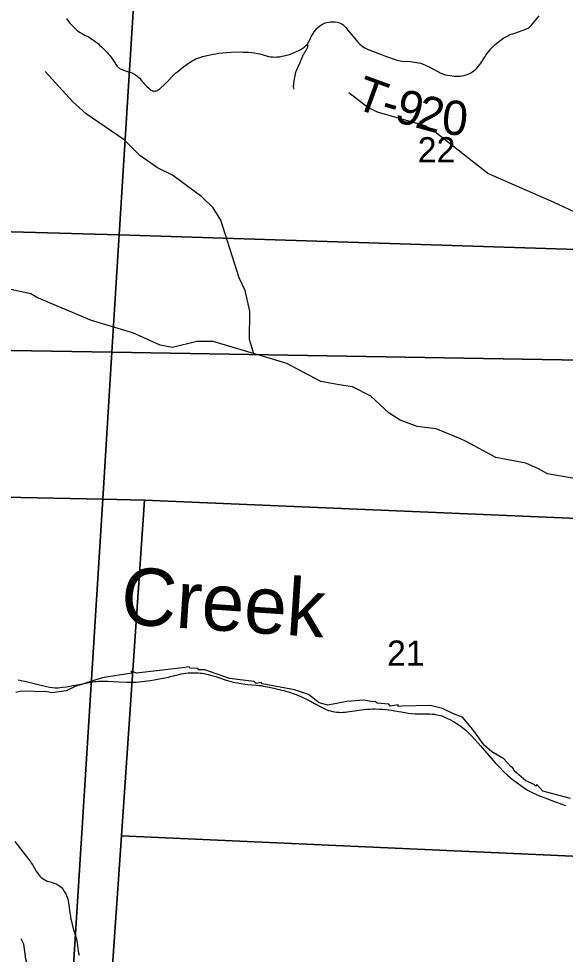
# Model space of a CAD drawing. Extents: x -2.1 to 31.9, y 6.3 to 28.3.
# Drawn here: x 1.171 to 2.076, y 21.978 to 23.525 of the extents above; entities that cross this region are included whole.
import ezdxf

# ---------------------------------------------------------------- set-up
doc = ezdxf.new("R2010")
doc.units = 0
for name, color, linetype in [('GM_X_County_Road', 7, 'Continuous'), ('GM_X_Minor_River', 7, 'Continuous'), ('GM_X_Minor_River_Text', 7, 'Continuous'), ('GM_X_Section', 7, 'Continuous'), ('GM_X_Section_Text', 7, 'Continuous'), ('GM_X_Township_Road', 7, 'Continuous'), ('GM_X_Township_Road_Text', 7, 'Continuous')]:
    doc.layers.add(name, color=color, linetype=linetype)

msp = doc.modelspace()

# ---------------------------------------------------------------- linework, layer by layer
at = {"layer": 'GM_X_County_Road'}
for points in [[(1.3504, 22.4281), (1.3554, 22.4281), (1.3656, 22.4282), (1.3701, 22.4286), (1.3749, 22.4291), (1.3895, 22.4309), (1.3952, 22.4318), (1.4009, 22.4327), (1.4165, 22.4357), (1.4193, 22.4363), (1.4224, 22.4372), (1.4369, 22.4409), (1.4403, 22.4416), (1.444, 22.4423), (1.4479, 22.4428), (1.4519, 22.4432), (1.4562, 22.4434), (1.4607, 22.4434), (1.4651, 22.4433), (1.4689, 22.4432), (1.4719, 22.4429), (1.4749, 22.4426), (1.4774, 22.4422), (1.4803, 22.4416), (1.4846, 22.4407), (1.4887, 22.4397), (1.4925, 22.4387), (1.4976, 22.4371), (1.511, 22.4325), (1.5169, 22.4307), (1.5207, 22.4296), (1.5247, 22.4285), (1.5291, 22.4275), (1.5333, 22.4266), (1.5392, 22.4256), (1.5426, 22.4251), (1.5462, 22.4246), (1.5502, 22.4242), (1.5643, 22.4231), (1.5686, 22.4227), (1.5725, 22.4222), (1.5759, 22.4216), (1.5862, 22.4198), (1.5981, 22.4172), (1.6102, 22.4142), (1.6207, 22.4109), (1.6303, 22.4074), (1.638, 22.4042), (1.6473, 22.4001), (1.6539, 22.3966), (1.6606, 22.3929), (1.6734, 22.3859), (1.6787, 22.3834), (1.684, 22.3813), (1.6874, 22.3803), (1.6909, 22.3794), (1.6941, 22.3787), (1.6976, 22.3782), (1.701, 22.3781), (1.7044, 22.378), (1.7082, 22.3781), (1.7117, 22.3784), (1.7147, 22.3788), (1.7347, 22.3818), (1.7386, 22.3824), (1.7427, 22.3828), (1.7474, 22.3832), (1.7526, 22.3835), (1.7568, 22.3836), (1.7612, 22.3836), (1.7675, 22.3835), (1.7736, 22.3833), (1.7785, 22.3829), (1.7832, 22.3824), (1.7883, 22.3816), (1.7937, 22.3807), (1.8109, 22.3777), (1.816, 22.3769), (1.8214, 22.3762), (1.827, 22.3758), (1.8327, 22.3756), (1.8515, 22.3754), (1.8554, 22.3752), (1.8593, 22.3749), (1.8633, 22.3741), (1.8671, 22.3732), (1.8715, 22.372), (1.8759, 22.3703), (1.881, 22.3681), (1.8857, 22.3656), (1.891, 22.3627), (1.8977, 22.3585), (1.9037, 22.3544), (1.9091, 22.3501), (1.9145, 22.3452), (1.9216, 22.338), (1.9354, 22.3228), (1.9597, 22.2948), (1.9673, 22.2866), (1.9735, 22.2804), (1.9803, 22.274), (1.988, 22.2676), (1.9983, 22.2596), (2.0059, 22.2542), (2.0133, 22.2494), (2.0198, 22.2458), (2.0231, 22.2442), (2.0268, 22.2426), (2.0305, 22.241), (2.0345, 22.2394), (2.0535, 22.2325), (2.0642, 22.2285), (2.0759, 22.2238)], [(1.1705, 22.4319), (1.1755, 22.4308), (1.1811, 22.4295), (1.199, 22.4251), (1.217, 22.4206), (1.2222, 22.4196), (1.2269, 22.419), (1.2318, 22.4187), (1.2364, 22.4188), (1.2438, 22.4195), (1.2496, 22.4204), (1.271, 22.4243), (1.2907, 22.428), (1.2938, 22.4286), (1.2967, 22.429), (1.3, 22.4293), (1.3032, 22.4295), (1.3075, 22.4297), (1.3119, 22.4297), (1.3155, 22.4297), (1.3188, 22.4295), (1.3363, 22.4284), (1.3504, 22.4281)], [(1.165, 22.1642), (1.1779, 22.1472), (1.1894, 22.1322), (1.1911, 22.1301), (1.1925, 22.1282), (1.1944, 22.1253), (1.2001, 22.1155), (1.2016, 22.1134), (1.203, 22.1115), (1.2064, 22.1073), (1.2086, 22.1051), (1.211, 22.1031), (1.2131, 22.1016), (1.2158, 22.1002), (1.2185, 22.099), (1.2213, 22.0981), (1.2248, 22.097), (1.2276, 22.0962), (1.2305, 22.0953), (1.2334, 22.0942), (1.2362, 22.0928), (1.2393, 22.0908), (1.242, 22.0884), (1.2447, 22.0851), (1.2467, 22.082), (1.249, 22.0777), (1.2503, 22.075), (1.2513, 22.0723), (1.2523, 22.0692), (1.2529, 22.0664), (1.2534, 22.063), (1.2563, 22.0434), (1.2567, 22.0408), (1.2571, 22.0381), (1.2589, 22.0305), (1.2598, 22.027), (1.2626, 22.017), (1.2653, 22.0087), (1.2659, 22.0062), (1.2667, 22.0032), (1.2674, 21.9999), (1.2679, 21.9964), (1.2697, 21.9836), (1.2703, 21.9797), (1.2711, 21.9767)]]:
    msp.add_lwpolyline(points, dxfattribs=at)
at = {"layer": 'GM_X_Minor_River'}
for points in [[(1.5606, 22.9712), (1.5532, 22.9949), (1.5535, 23.0416), (1.5462, 23.076), (1.5359, 23.0968), (1.5059, 23.1919), (1.4929, 23.2124), (1.4745, 23.2305), (1.4257, 23.2666), (1.4008, 23.2788), (1.3715, 23.299), (1.3455, 23.3249), (1.2829, 23.3679), (1.2608, 23.3876), (1.2151, 23.438)], [(2.2292, 22.675), (2.2438, 22.6952), (2.2584, 22.7344), (2.261, 22.8616), (2.2631, 22.9011), (2.2682, 22.9261), (2.294, 22.9878), (2.2915, 23.0269), (2.2788, 23.0655), (2.2562, 23.0966), (2.2413, 23.1128), (2.2074, 23.1381), (2.0996, 23.2016), (2.0573, 23.2215), (1.9474, 23.2691), (1.86, 23.3382), (1.844, 23.3483), (1.765, 23.3707), (1.749, 23.3785), (1.7173, 23.4027)], [(2.0935, 22.7644), (2.0465, 22.7727), (2.0316, 22.7808), (2.0107, 22.7902), (1.9611, 22.7997), (1.9117, 22.826), (1.9024, 22.8304), (1.862, 22.8469), (1.8308, 22.8509), (1.8024, 22.8613), (1.7842, 22.8729), (1.7537, 22.9008), (1.7235, 22.9162), (1.7017, 22.9196), (1.6713, 22.9254), (1.6147, 22.9549), (1.6024, 22.9588), (1.493, 22.9914), (1.4658, 22.9912), (1.4258, 22.9814), (1.4055, 22.9855), (1.36, 23.0059), (1.3521, 23.0081), (1.2918, 23.0259), (1.2011, 23.0641), (1.1915, 23.0701), (1.1584, 23.0776)], [(2.0843, 22.2358), (2.0385, 22.2479), (2.0287, 22.2585), (2.0268, 22.2562), (2.0242, 22.2585), (2.0105, 22.2645), (1.9909, 22.2812), (1.989, 22.2865), (1.986, 22.288), (1.9738, 22.3013), (1.9542, 22.313), (1.9417, 22.3236), (1.9228, 22.3498), (1.9054, 22.3699), (1.8906, 22.3756), (1.8728, 22.3846), (1.852, 22.3891), (1.8052, 22.3883), (1.7991, 22.3879), (1.7991, 22.3905), (1.7859, 22.3882), (1.7836, 22.3916), (1.7647, 22.3931), (1.7609, 22.3961), (1.7572, 22.3957), (1.7424, 22.398), (1.7144, 22.396), (1.6827, 22.3898), (1.6687, 22.394), (1.6509, 22.4076), (1.6279, 22.4155), (1.5742, 22.4253), (1.5727, 22.4275), (1.564, 22.426), (1.5606, 22.429), (1.5201, 22.4339), (1.4793, 22.4482), (1.4695, 22.4482), (1.4679, 22.4504), (1.4543, 22.4512), (1.4532, 22.4534), (1.4422, 22.4515), (1.3659, 22.4429), (1.3576, 22.446), (1.3583, 22.4429), (1.3096, 22.4352), (1.2646, 22.421), (1.2495, 22.4134), (1.2268, 22.4103), (1.2185, 22.4118), (1.1761, 22.4132), (1.1663, 22.4109)], [(1.4787, 21.3956), (1.4522, 21.4549), (1.4452, 21.4874), (1.4392, 21.513), (1.4232, 21.5572), (1.3999, 21.599), (1.3573, 21.6542), (1.3397, 21.6829), (1.3277, 21.7121), (1.3155, 21.733), (1.2879, 21.7589), (1.2752, 21.776), (1.2624, 21.8023), (1.223, 21.887), (1.206, 21.9111), (1.2024, 21.9192), (1.19, 21.9443), (1.1828, 21.9696), (1.1798, 21.9947), (1.1755, 22.0032)]]:
    msp.add_lwpolyline(points, dxfattribs=at)
at = {"layer": 'GM_X_Section'}
for points in [[(1.3641, 23.5904), (1.3376, 23.1681), (0.3083, 23.1964), (0.3317, 23.6098)], [(1.3641, 23.5904), (2.3938, 23.5483), (2.3709, 23.1348), (1.3376, 23.1681)], [(0.3083, 23.1964), (1.3376, 23.1681), (1.3254, 22.9735), (0.2949, 22.9906)], [(1.3376, 23.1681), (2.3709, 23.1348), (2.3614, 22.9562), (1.3254, 22.9735)], [(0.2947, 22.9877), (0.2949, 22.9906), (1.3254, 22.9735), (1.3102, 22.7307), (0.8218, 22.7408), (0.2809, 22.7519)], [(2.3614, 22.9562), (2.3612, 22.9526), (2.3441, 22.6882), (2.1616, 22.6959), (1.3796, 22.7292), (1.3102, 22.7307), (1.3254, 22.9735)], [(1.3102, 22.7307), (1.2591, 21.9158), (0.7728, 21.931), (0.8218, 22.7408)], [(1.3796, 22.7292), (1.3414, 22.174), (1.3233, 21.9111), (1.2618, 21.9156), (1.2591, 21.9158), (1.3102, 22.7307)], [(2.1616, 22.6959), (2.1245, 22.1384), (1.3414, 22.174), (1.3796, 22.7292)], [(1.3414, 22.174), (2.1245, 22.1384), (2.3089, 22.1301), (2.2923, 21.8673), (1.3233, 21.9111)]]:
    msp.add_lwpolyline(points, close=True, dxfattribs=at)
at = {"layer": 'GM_X_Township_Road'}
for points in [[(1.2501, 23.5257), (1.2561, 23.518), (1.2601, 23.5133), (1.2645, 23.509), (1.2687, 23.5054), (1.2728, 23.5026), (1.277, 23.5), (1.2793, 23.4987), (1.2817, 23.4975), (1.2847, 23.4962), (1.2879, 23.4945), (1.2908, 23.4928), (1.2935, 23.4911), (1.2966, 23.4889), (1.2996, 23.4866), (1.3026, 23.4841), (1.3051, 23.4818), (1.3082, 23.4788), (1.3112, 23.4759), (1.3144, 23.4727), (1.3176, 23.4694), (1.3199, 23.4669), (1.3221, 23.4643), (1.3238, 23.4622), (1.3255, 23.4599), (1.3276, 23.4568), (1.3294, 23.4541), (1.3309, 23.4518), (1.3321, 23.4498), (1.3335, 23.4476), (1.3351, 23.4457), (1.3369, 23.4441), (1.3381, 23.4432), (1.3393, 23.4424), (1.3409, 23.4417), (1.3424, 23.4411), (1.3446, 23.4404), (1.3497, 23.4387), (1.3548, 23.437), (1.3567, 23.4363), (1.3587, 23.4355), (1.3607, 23.4344), (1.3627, 23.4334), (1.3646, 23.4323), (1.3666, 23.431), (1.3685, 23.4294), (1.3702, 23.428), (1.3714, 23.4268), (1.3726, 23.4254), (1.3737, 23.4239), (1.3754, 23.4217), (1.377, 23.4198), (1.3789, 23.4176), (1.3834, 23.4132), (1.3864, 23.4105), (1.389, 23.4083), (1.3907, 23.4071), (1.3926, 23.4062), (1.3937, 23.4059), (1.3948, 23.4057), (1.3959, 23.4057), (1.3969, 23.4057), (1.3981, 23.4059), (1.3992, 23.4061), (1.4007, 23.4067), (1.4021, 23.4074), (1.4033, 23.4081), (1.4044, 23.4088), (1.4055, 23.4097), (1.4129, 23.4172), (1.4314, 23.4355), (1.4343, 23.438), (1.4376, 23.4407), (1.4418, 23.444), (1.4479, 23.4487), (1.452, 23.4515), (1.4552, 23.4536), (1.4583, 23.4555), (1.4614, 23.4573), (1.4646, 23.4589), (1.4676, 23.4602), (1.471, 23.4614), (1.4755, 23.4626), (1.4932, 23.4666), (1.4974, 23.4674), (1.502, 23.4682), (1.5085, 23.4691), (1.5147, 23.4696), (1.5222, 23.4699), (1.5379, 23.4703), (1.5428, 23.4702), (1.5471, 23.4701), (1.5517, 23.4698), (1.5565, 23.4694), (1.5616, 23.4687), (1.5666, 23.4679), (1.5705, 23.467), (1.5741, 23.466), (1.5776, 23.465), (1.5813, 23.4639), (1.5848, 23.463), (1.588, 23.4623), (1.5917, 23.462), (1.595, 23.4619), (1.5984, 23.4621), (1.603, 23.4625), (1.6074, 23.4632), (1.613, 23.4643), (1.6171, 23.4656), (1.621, 23.4669), (1.626, 23.4688), (1.631, 23.471), (1.6358, 23.4733), (1.6387, 23.4749), (1.6414, 23.4767), (1.6441, 23.4788), (1.6463, 23.4808), (1.6496, 23.4839), (1.6537, 23.492), (1.6559, 23.4963), (1.6585, 23.5008), (1.6604, 23.5036), (1.6623, 23.5061), (1.6648, 23.5089), (1.667, 23.5111), (1.6691, 23.5129), (1.6713, 23.5145), (1.6737, 23.516), (1.6761, 23.5172), (1.6785, 23.5182), (1.6812, 23.5192), (1.6842, 23.5198), (1.6872, 23.5201), (1.6899, 23.5202), (1.6924, 23.5201), (1.6949, 23.5199), (1.698, 23.5195), (1.7007, 23.519), (1.7033, 23.518), (1.7058, 23.5167), (1.708, 23.5151), (1.7103, 23.5131), (1.7124, 23.5108), (1.7144, 23.5085), (1.7164, 23.506), (1.7299, 23.4896), (1.7332, 23.4861), (1.736, 23.4832), (1.7386, 23.4808), (1.7414, 23.4787), (1.7438, 23.4773), (1.7461, 23.476), (1.7497, 23.4744), (1.7801, 23.4628), (1.7945, 23.4577), (1.7971, 23.4568), (1.7998, 23.4561), (1.8025, 23.4557), (1.806, 23.4553), (1.8203, 23.4543), (1.8231, 23.454), (1.8264, 23.4536), (1.8296, 23.4531), (1.8329, 23.4524), (1.8361, 23.4515), (1.8394, 23.4504), (1.8467, 23.4475), (1.8493, 23.4463), (1.8518, 23.445), (1.8542, 23.4437), (1.8668, 23.4367), (1.8689, 23.4355), (1.8716, 23.4344), (1.8742, 23.4336), (1.8773, 23.4327), (1.881, 23.432), (1.8853, 23.4313), (1.8888, 23.4307), (1.8918, 23.4304), (1.8951, 23.4302), (1.8983, 23.4302), (1.902, 23.4304), (1.9051, 23.4308), (1.9086, 23.4316), (1.912, 23.4327), (1.9159, 23.4342), (1.9193, 23.4359), (1.9227, 23.4379), (1.9251, 23.4397), (1.9277, 23.4418), (1.93, 23.4441), (1.9324, 23.4469), (1.9345, 23.4497), (1.9361, 23.4518), (1.9421, 23.4612), (1.9444, 23.4648), (1.9465, 23.4678), (1.9487, 23.4707), (1.9507, 23.4732), (1.9526, 23.4754), (1.9548, 23.4777), (1.9574, 23.4803), (1.9596, 23.4824), (1.9626, 23.4851), (1.9662, 23.4879), (1.9689, 23.4899), (1.9716, 23.492), (1.9739, 23.4935), (1.9763, 23.4949), (1.9784, 23.496), (1.9807, 23.4971), (1.9834, 23.4984), (1.986, 23.4995), (1.9889, 23.5005), (1.992, 23.5016), (2.0107, 23.5082), (2.0128, 23.509), (2.0144, 23.5098), (2.0161, 23.511), (2.0176, 23.5125), (2.0191, 23.514), (2.0328, 23.5299)], [(1.627, 23.4086), (1.6262, 23.413), (1.6262, 23.4148), (1.6263, 23.4166), (1.6266, 23.4184), (1.6278, 23.4259), (1.6291, 23.4336), (1.6294, 23.4353), (1.6298, 23.4369), (1.6303, 23.4384), (1.6308, 23.4396), (1.6329, 23.4445), (1.6362, 23.452), (1.6414, 23.4639), (1.6422, 23.4655), (1.643, 23.4669), (1.6443, 23.4689), (1.6456, 23.471), (1.6481, 23.4752), (1.6487, 23.4762), (1.6492, 23.4774), (1.6495, 23.4786), (1.6496, 23.4794), (1.6497, 23.4803), (1.6497, 23.4817), (1.6496, 23.4839)]]:
    msp.add_lwpolyline(points, dxfattribs=at)

# ---------------------------------------------------------------- texts
at = {"layer": 'GM_X_Minor_River_Text'}
msp.add_text('Creek', height=0.09469, rotation=356.1515, dxfattribs=at).set_placement((1.3383, 22.5245))
at = {"layer": 'GM_X_Section_Text'}
for s, p in [('22', (1.8316, 23.2875)), ('21', (1.7808, 22.455))]:
    msp.add_text(s, height=0.04186, rotation=0, dxfattribs=at).set_placement(p)
at = {"layer": 'GM_X_Township_Road_Text'}
for s, rotation, p in [('T', 340.1352, (1.7245, 23.3785)), ('9', 343.8492, (1.7907, 23.3562)), ('2', 344.5951, (1.8251, 23.3463)), ('-', 343.5921, (1.7681, 23.3629)), ('0', 354.9875, (1.8699, 23.335))]:
    msp.add_text(s, height=0.0568, rotation=rotation, dxfattribs=at).set_placement(p)

doc.saveas('drawing.dxf')
